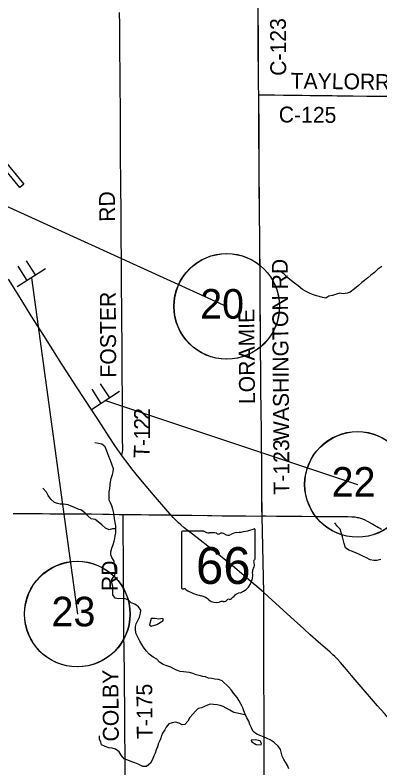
# Model space of a CAD drawing. Extents: x -87 to 2145, y -2128 to 440.
# Drawn here: x 137.8 to 172.4, y 214.2 to 285.5 of the extents above; entities that cross this region are included whole.
import ezdxf

# ---------------------------------------------------------------- set-up
doc = ezdxf.new("R2010")
doc.units = 0
for name, color, linetype in [('GM_X_County_Road', 7, 'Continuous'), ('GM_X_County_Road_Text', 7, 'Continuous'), ('GM_X_Minor_Lake', 7, 'Continuous'), ('GM_X_Minor_River', 7, 'Continuous'), ('GM_X_State_Route', 7, 'Continuous'), ('GM_X_State_Shield', 7, 'Continuous'), ('GM_X_Township', 7, 'Continuous'), ('GM_X_Township_Road', 7, 'Continuous'), ('GM_X_Township_Road_Text', 7, 'Continuous'), ('GM_X_Township_Text', 7, 'Continuous'), ('MT_P_Cells', 7, 'Continuous'), ('SH_Masking', 7, 'Continuous'), ('SH_Text', 7, 'Continuous'), ('SN_P_Signs', 7, 'Continuous')]:
    doc.layers.add(name, color=color, linetype=linetype)

msp = doc.modelspace()

# ---------------------------------------------------------------- linework, layer by layer
at = {"layer": 'GM_X_County_Road'}
for points in [[(160.956, 277.99), (160.937, 278.874), (160.929, 280.301), (160.914, 281.909), (160.908, 283.155), (160.896, 286.075), (160.878, 287.764), (160.868, 288.65), (160.857, 289.749), (160.856, 291.24)], [(160.956, 277.99), (161.326, 277.989), (161.494, 277.988), (162.43, 277.979), (163.284, 277.974), (165.072, 277.955), (165.81, 277.944), (167.402, 277.923), (167.894, 277.916), (168.386, 277.909), (168.993, 277.907), (169.911, 277.89), (171.191, 277.877), (172.389, 277.863), (173.341, 277.856), (173.75, 277.848), (173.989, 277.845), (174.18, 277.842)], [(137.665, 238.34), (139.125, 238.325), (139.715, 238.321), (140.42, 238.316), (141.125, 238.313), (142.143, 238.308), (142.454, 238.306), (143.421, 238.301), (144.176, 238.301), (145.095, 238.289), (146.161, 238.272), (146.784, 238.264), (147.702, 238.251), (148.1, 238.246)], [(148.1, 238.246), (148.375, 238.243), (149.031, 238.237), (149.785, 238.227), (150.539, 238.219), (151.409, 238.207), (152.442, 238.192), (152.628, 238.189)], [(152.628, 238.189), (153.115, 238.182), (154.607, 238.163), (156.083, 238.139), (156.493, 238.132), (157.477, 238.125), (158.445, 238.118), (159.708, 238.107), (160.791, 238.094), (161.275, 238.102)], [(161.275, 238.102), (161.619, 238.098), (162.636, 238.084), (163.308, 238.084), (164.423, 238.07), (165.047, 238.064), (166.408, 238.055), (167.146, 238.05), (167.917, 238.047), (168.671, 238.042), (169.409, 238.036), (169.785, 238.025), (170.062, 238.003), (170.286, 237.968), (170.397, 237.943), (170.585, 237.89), (170.798, 237.811), (171.007, 237.718), (171.241, 237.602), (171.759, 237.32), (172.305, 237.018), (172.593, 236.861)]]:
    msp.add_lwpolyline(points, dxfattribs=at)
at = {"layer": 'GM_X_Minor_Lake'}
for points in [[(151.08, 228.376), (150.759, 228.393), (150.575, 227.773), (150.733, 227.659), (151.289, 227.818)], [(151.289, 227.818), (151.859, 228.168), (151.922, 228.318), (151.793, 228.391), (151.46, 228.317), (151.08, 228.376)], [(160.609, 216.877), (160.237, 216.855), (160.303, 216.693), (160.69, 216.463)], [(160.69, 216.463), (161.171, 216.402), (161.214, 216.532), (161.069, 216.786), (160.609, 216.877)]]:
    msp.add_lwpolyline(points, dxfattribs=at)
at = {"layer": 'GM_X_Minor_River'}
for points in [[(172.628, 261.722), (172.251, 261.468), (171.924, 261.172), (171.587, 260.907), (171.3, 260.652), (170.973, 260.396), (170.708, 260.201), (170.361, 259.906), (170.033, 259.61), (169.615, 259.307), (169.322, 259.212), (168.959, 259.149), (168.638, 259.196), (168.306, 259.123), (167.931, 258.99), (167.588, 258.906), (167.323, 258.74), (166.983, 258.778), (166.684, 258.885), (166.424, 258.951), (166.035, 259.09), (165.746, 259.206), (165.429, 259.374), (165.081, 259.563), (164.696, 259.893), (164.35, 260.162), (164.054, 260.38), (163.698, 260.659), (163.384, 260.988), (163.057, 261.236), (162.708, 261.344)], [(147.349, 236.215), (147.395, 236.496), (147.402, 236.828), (147.388, 237.15), (147.335, 237.493), (147.283, 237.866), (147.213, 238.36), (147.11, 238.735), (147.017, 239.068), (146.902, 239.332), (146.777, 239.586), (146.765, 239.979), (146.763, 240.381), (146.831, 240.712), (146.858, 241.043), (146.884, 241.325), (146.951, 241.655), (147.069, 242.015), (147.155, 242.285), (147.191, 242.566), (147.029, 243.002), (146.876, 243.367), (146.723, 243.722), (146.638, 243.976), (146.525, 244.32), (146.381, 244.645), (146.085, 244.903), (145.755, 244.96), (145.405, 245.017)], [(147.399, 236.886), (147.071, 236.875), (146.778, 236.79), (146.43, 236.958), (146.065, 237.268), (145.73, 237.546), (145.433, 237.763), (145.073, 237.841), (144.787, 238.068), (144.482, 238.376), (144.136, 238.655), (143.837, 238.741), (143.429, 238.921), (143.17, 239.027), (142.881, 239.143), (142.441, 239.202), (142.13, 239.229), (141.87, 239.284), (141.581, 239.381), (141.236, 239.69), (140.992, 240.046), (140.808, 240.362), (140.484, 240.721)], [(172.509, 233.983), (172.155, 233.87), (171.854, 233.876), (171.514, 233.944), (171.156, 234.123), (170.867, 234.25), (170.49, 234.459), (170.201, 234.586), (169.843, 234.734), (169.494, 234.853), (169.167, 235.071), (169.045, 235.476), (168.99, 235.749), (168.898, 236.123), (168.756, 236.519), (168.662, 236.853), (168.387, 237.121), (168.152, 237.448)], [(163.785, 214.145), (163.661, 214.449), (163.477, 214.784), (163.332, 215.039), (163.177, 215.343), (163.075, 215.727), (163.01, 215.98), (162.775, 216.286), (162.421, 216.626), (162.035, 216.875), (161.746, 217.002), (161.388, 217.161), (161.04, 217.309), (160.751, 217.436), (160.425, 217.674), (160.272, 218.039), (160.117, 218.344), (159.994, 218.668), (159.819, 218.973), (159.656, 219.308), (159.522, 219.653), (159.438, 219.936), (159.294, 220.25), (159.08, 220.586), (158.916, 220.891), (158.563, 221.321), (158.368, 221.587), (158.094, 221.924), (157.483, 222.48), (157.134, 222.598), (156.774, 222.646), (156.514, 222.702), (156.173, 222.739), (155.894, 222.866), (155.634, 222.892), (155.304, 222.979), (155.015, 223.056), (154.686, 223.184), (154.386, 223.26), (154.086, 223.307), (153.825, 223.323), (153.495, 223.36), (153.156, 223.488), (152.887, 223.604), (152.599, 223.761), (152.241, 223.909), (151.892, 224.037), (151.535, 224.246), (151.27, 224.523), (150.932, 224.711), (150.567, 225.02), (150.272, 225.308), (150.008, 225.665), (149.853, 225.92), (149.679, 226.245), (149.486, 226.621), (149.322, 226.946), (149.249, 227.289), (149.246, 227.621), (149.322, 227.88), (149.489, 228.188), (149.646, 228.507), (149.745, 228.876), (149.781, 229.187), (149.557, 229.483), (149.2, 229.732), (148.862, 229.88), (148.557, 230.158), (148.187, 230.266), (147.645, 230.257), (147.345, 230.324), (147.11, 230.62), (147.108, 231.012), (147.097, 231.425), (147.024, 231.748), (147.021, 232.09), (147.29, 232.476), (147.358, 232.847), (147.324, 233.139), (147.281, 233.502), (147.248, 233.824), (147.024, 234.161), (146.909, 234.414), (146.935, 234.705), (147.013, 235.046), (147.141, 235.405), (147.227, 235.695), (147.293, 235.965), (147.349, 236.215)], [(159.667, 219.285), (159.594, 219.249), (159.224, 219.338), (158.894, 219.405), (158.575, 219.492), (158.208, 219.691), (157.583, 220.057), (157.293, 220.153), (157.004, 220.22), (156.643, 220.248), (156.341, 220.255), (156.089, 220.19), (155.815, 220.035), (155.521, 219.931), (155.218, 219.867), (154.952, 219.592), (154.705, 219.336), (154.417, 219.011), (154.209, 218.674), (153.951, 218.349), (153.689, 218.314), (153.401, 218.481), (153.062, 218.569), (152.739, 218.516), (152.416, 218.402), (152.178, 218.106), (152.032, 217.828), (151.815, 217.532), (151.729, 217.283), (151.632, 216.954), (151.453, 216.566), (151.335, 216.228), (151.218, 215.929), (151.111, 215.631), (150.995, 215.362), (150.868, 215.024), (150.669, 214.677), (150.301, 214.374), (149.96, 214.372), (149.512, 214.582), (149.214, 214.709), (148.915, 214.816), (148.546, 214.955), (148.187, 215.083), (147.893, 215.43), (147.7, 215.766), (147.364, 216.014), (147.034, 216.101), (146.734, 216.148), (146.374, 216.256), (146.046, 216.414), (145.961, 216.666), (145.857, 216.939), (145.833, 217.261)]]:
    msp.add_lwpolyline(points, dxfattribs=at)
at = {"layer": 'GM_X_State_Route'}
for points in [[(161.451, 230.818), (161.419, 230.846), (160.947, 231.253), (160.235, 231.859), (158.438, 233.391), (157.831, 233.893), (156.975, 234.581), (156.119, 235.243), (154.661, 236.361), (154.285, 236.653), (153.889, 236.974), (153.564, 237.251), (153.345, 237.45), (153.143, 237.643), (152.88, 237.914), (152.628, 238.189), (152.558, 238.266), (152.138, 238.749), (150.983, 240.092), (149.913, 241.337), (149.328, 242.045), (148.908, 242.571), (148.458, 243.157), (148.136, 243.593), (147.969, 243.829), (147.747, 244.142), (147.312, 244.779), (146.769, 245.6), (146.024, 246.739), (145.556, 247.452), (145.115, 248.124), (143.668, 250.333), (142.737, 251.743), (142.262, 252.472), (140.555, 255.196), (139.374, 257.07), (138.827, 257.947), (138.061, 259.17), (137.213, 260.517)], [(177.485, 213.875), (176.042, 215.597), (175.403, 216.367), (174.703, 217.214), (174.597, 217.339), (173.97, 218.076), (172.861, 219.373), (172.217, 220.117), (169.91, 222.806), (169.257, 223.564), (168.699, 224.208), (168.413, 224.524), (168.173, 224.77), (167.985, 224.951), (167.73, 225.182), (167.248, 225.602), (166.613, 226.148), (165.813, 226.853), (165.217, 227.393), (163.994, 228.51), (163.255, 229.185), (161.837, 230.477), (161.451, 230.818)]]:
    msp.add_lwpolyline(points, dxfattribs=at)
at = {"layer": 'GM_X_State_Shield'}
for p, q in [((160.598, 234.032), (160.598, 236.796)), ((153.638, 236.574), (153.638, 231.291)), ((155.745, 236.665), (153.706, 236.665)), ((160.598, 234.033), (160.598, 234.032))]:
    msp.add_line(p, q, dxfattribs=at)
for centre, radius, start, end in [((158.119, 243.867), 7.382, 275.84447, 288.90645), ((160.521, 236.807), 0.0775, 351.86209, 97.738), ((153.717, 236.585), 0.0806, 98.1301, 188.1301), ((156.23, 237.278), 0.782, 231.61951, 271.11188), ((156.49, 233.699), 2.808, 80.48669, 94.98827), ((157.127, 236.612), 0.226, 219.79206, 297.10237), ((157.458, 236.002), 0.469, 54.46668, 119.14113), ((158.064, 236.839), 0.564, 233.85621, 294.82819), ((159.061, 235.051), 1.485, 97.34618, 120.76885), ((160.581, 233.829), 0.12, 107.94398, 210.33697), ((160.516, 234.021), 0.0829, 289.60381, 7.73413), ((160.876, 232.875), 0.524, 136.8065, 186.92959), ((159.818, 233.48), 0.72, 340.03296, 23.64957), ((158.532, 232.524), 1.846, 292.30889, 8.98584), ((153.718, 231.279), 0.0814, 171.95839, 258.30661), ((153.73, 231.82), 0.621, 267.33899, 280.60386), ((153.858, 230.986), 0.224, 29.74838, 93.27175), ((156.684, 235.733), 5.331, 240.41292, 257.1985), ((155.095, 228.917), 1.668, 47.18416, 75.83597), ((158.03, 230.779), 0.597, 282.87319, 323.27711), ((159.311, 229.807), 1.011, 94.40312, 142.57675), ((156.899, 230.96), 1.058, 230.70037, 286.29184), ((157.51, 229.133), 0.87, 85.69512, 111.20995), ((157.587, 230.564), 0.564, 268.77702, 315.54927), ((158.097, 230.052), 0.159, 65.75173, 132.64842)]:
    msp.add_arc(centre, radius, start, end, dxfattribs=at)
at = {"layer": 'GM_X_Township'}
msp.add_lwpolyline([(161.454, 211.501), (161.445, 230.832), (161.269, 238.116), (161.255, 238.765), (161.246, 240.094), (161.239, 241.061), (161.238, 241.767), (161.232, 242.636), (161.225, 243.456), (161.216, 244.473), (161.204, 245.489), (161.199, 246.604), (161.183, 247.638), (161.166, 248.588), (161.153, 249.589), (161.153, 249.9), (161.151, 250.622), (161.144, 251.475), (161.134, 252.377), (161.122, 253.295), (161.114, 254.017), (161.109, 254.509), (161.105, 256.149), (161.096, 256.903), (161.09, 257.477), (161.084, 258.855), (161.077, 259.609), (161.071, 260.117), (161.075, 260.937), (161.07, 261.527), (161.06, 262.232), (161.052, 262.708), (161.045, 263.512), (161.04, 264.168), (161.039, 264.856), (161.037, 265.168), (161.026, 266.07), (161.01, 267.611), (161.002, 268.612), (160.993, 269.989), (160.975, 272.138), (160.968, 273.548), (160.968, 275.418), (160.968, 275.959), (160.957, 276.483), (160.956, 277.303), (160.951, 277.713), (160.95, 278.005), (160.931, 278.889), (160.923, 280.316), (160.907, 281.923), (160.902, 283.17), (160.889, 286.089)], dxfattribs=at)
at = {"layer": 'GM_X_Township_Road'}
for points in [[(147.969, 243.829), (148.004, 244.013), (148.034, 244.175), (148.047, 244.305), (148.051, 244.616), (148.044, 245.273), (148.039, 246.257), (148.036, 247.241), (148.026, 248.52), (148.021, 249.209), (148.015, 249.832), (148.014, 250.078), (148.008, 250.816), (148.005, 251.472), (148.002, 252.505), (148, 253.243), (147.99, 254.309), (147.983, 255.031), (147.974, 255.933), (147.966, 256.72), (147.963, 257.507), (147.956, 258.311), (147.948, 259.18), (147.941, 260.279), (147.934, 261.083), (147.919, 262.542), (147.914, 264.281), (147.913, 264.97), (147.907, 265.692), (147.899, 266.659), (147.894, 267.414), (147.878, 268.906), (147.871, 269.956), (147.857, 270.71), (147.85, 271.202), (147.848, 271.792), (147.851, 272.416), (147.849, 272.924), (147.834, 274.613), (147.832, 276.467), (147.83, 277.123), (147.819, 278.304), (147.814, 279.452), (147.808, 280.305), (147.792, 281.879), (147.772, 284.618), (147.757, 285.783)], [(161.086, 259.244), (161.083, 259.595), (161.077, 260.103), (161.081, 260.923), (161.076, 261.513), (161.066, 262.218), (161.058, 262.694), (161.051, 263.497), (161.046, 264.153), (161.046, 264.842), (161.043, 265.154), (161.032, 266.056), (161.016, 267.597), (161.008, 268.598), (160.999, 269.975), (160.981, 272.123), (160.974, 273.534), (160.974, 275.403), (160.974, 275.945), (160.963, 276.469), (160.962, 277.289), (160.957, 277.699), (160.956, 277.99)], [(161.275, 238.102), (161.262, 238.751), (161.252, 240.08), (161.245, 241.047), (161.245, 241.752), (161.239, 242.622), (161.232, 243.442), (161.222, 244.458), (161.21, 245.475), (161.205, 246.59), (161.189, 247.623), (161.172, 248.574), (161.159, 249.575), (161.159, 249.886), (161.157, 250.608), (161.151, 251.461), (161.14, 252.362), (161.128, 253.281), (161.12, 254.002), (161.115, 254.494), (161.111, 256.134), (161.103, 256.889), (161.096, 257.463), (161.09, 258.84), (161.086, 259.244)], [(148.282, 213.568), (148.272, 214.404), (148.272, 215.142), (148.273, 215.552), (148.271, 216.191), (148.264, 216.831), (148.257, 217.503), (148.253, 218.405), (148.249, 218.88), (148.247, 219.438), (148.242, 220.094), (148.236, 220.652), (148.231, 221.308), (148.225, 222.177), (148.222, 222.619), (148.212, 223.439), (148.204, 223.98), (148.191, 224.538), (148.175, 225.635), (148.173, 225.914), (148.169, 226.34), (148.165, 226.832), (148.165, 227.259), (148.164, 227.669), (148.16, 228.34), (148.154, 228.93), (148.152, 229.422), (148.149, 229.93), (148.144, 230.52), (148.132, 231.668), (148.129, 232.275), (148.126, 232.701), (148.121, 233.242), (148.118, 233.471), (148.117, 233.93), (148.114, 234.635), (148.11, 235.144), (148.108, 235.472), (148.101, 236.538), (148.097, 237.194), (148.099, 238.063), (148.1, 238.246)]]:
    msp.add_lwpolyline(points, dxfattribs=at)
at = {"layer": 'GM_X_Township_Text'}
msp.add_lwpolyline([(161.454, 211.501), (161.445, 230.832), (161.269, 238.116), (161.255, 238.765), (161.246, 240.094), (161.239, 241.061), (161.238, 241.767), (161.232, 242.636), (161.225, 243.456), (161.216, 244.473), (161.204, 245.489), (161.199, 246.604), (161.183, 247.638), (161.166, 248.588), (161.153, 249.589), (161.153, 249.9), (161.151, 250.622), (161.144, 251.475), (161.134, 252.377), (161.122, 253.295), (161.114, 254.017), (161.109, 254.509), (161.105, 256.149), (161.096, 256.903), (161.09, 257.477), (161.084, 258.855), (161.077, 259.609), (161.071, 260.117), (161.075, 260.937), (161.07, 261.527), (161.06, 262.232), (161.052, 262.708), (161.045, 263.512), (161.04, 264.168), (161.039, 264.856), (161.037, 265.168), (161.026, 266.07), (161.01, 267.611), (161.002, 268.612), (160.993, 269.989), (160.975, 272.138), (160.968, 273.548), (160.968, 275.418), (160.968, 275.959), (160.957, 276.483), (160.956, 277.303), (160.951, 277.713), (160.95, 278.005), (160.931, 278.889), (160.923, 280.316), (160.907, 281.923), (160.902, 283.17), (160.889, 286.089)], dxfattribs=at)
at = {"layer": 'MT_P_Cells'}
msp.add_lwpolyline([(136.764, 271.848), (138.668, 269.53), (138.282, 269.213), (136.377, 271.53)], close=True, dxfattribs=at)
at = {"layer": 'SH_Masking'}
for centre in [(157.922, 257.951), (170.319, 241.085), (143.751, 228.801)]:
    msp.add_circle(centre, 5, dxfattribs=at)
at = {"layer": 'SH_Text'}
for p, q in [((136.192, 267.818), (157.922, 257.951)), ((139.389, 260.671), (143.751, 228.801)), ((146.417, 249.023), (170.319, 241.085))]:
    msp.add_line(p, q, dxfattribs=at)
for centre in [(157.903, 257.959), (170.3, 241.093), (143.732, 228.809)]:
    msp.add_circle(centre, 5, dxfattribs=at)
at = {"layer": 'SN_P_Signs'}
for p, q in [((138.983, 260.416), (138.13, 261.77)), ((139.795, 260.927), (138.942, 262.281)), ((140.743, 261.524), (138.035, 259.819)), ((139.389, 260.671), (139.389, 260.671)), ((139.389, 260.671), (139.389, 260.671)), ((146.818, 249.286), (145.942, 250.624)), ((147.755, 249.899), (145.078, 248.146)), ((146.015, 248.76), (145.139, 250.098)), ((146.417, 249.023), (146.417, 249.023)), ((146.417, 249.023), (146.417, 249.023))]:
    msp.add_line(p, q, dxfattribs=at)

# ---------------------------------------------------------------- texts
at = {"layer": 'GM_X_County_Road_Text'}
for s, rotation, p in [('C-123', 90.27563, (163.546, 279.796)), ('TAYLOR', 359.32756, (163.962, 278.58)), ('RD', 359.00161, (171.949, 278.469)), ('C-125', 359.44972, (162.839, 275.384))]:
    msp.add_text(s, height=1.5, rotation=rotation, dxfattribs=at).set_placement(p)
at = {"layer": 'GM_X_State_Shield'}
msp.add_text('66', height=3.4805, dxfattribs=at).set_placement((154.998, 231.663))
at = {"layer": 'GM_X_Township_Road_Text'}
for s, rotation, p in [('RD', 90.49261, (147.326, 265.966)), ('WASHINGTON RD', 90.48916, (163.832, 245.192)), ('FOSTER', 90.36729, (147.435, 251.209)), ('LORAMIE', 90.45215, (160.591, 248.701)), ('2', 89.99229, (150.629, 247.197)), ('2', 89.96118, (150.628, 246.272)), ('1', 89.83113, (150.626, 245.344)), ('T', 87.2905, (150.565, 243.535)), ('-', 89.47862, (150.62, 244.718)), ('T-123', 90.28004, (163.851, 240.119)), ('RD', 90.49493, (147.568, 230.988)), ('COLBY', 90.39999, (147.677, 216.737)), ('T-175', 90.56254, (150.893, 216.97))]:
    msp.add_text(s, height=1.5, rotation=rotation, dxfattribs=at).set_placement(p)
at = {"layer": 'SH_Text'}
for s, p in [('20', (155.39, 256.791)), ('22', (167.853, 239.925)), ('23', (141.293, 227.641))]:
    msp.add_text(s, height=2.8, rotation=360, dxfattribs=at).set_placement(p)

doc.saveas('drawing.dxf')
